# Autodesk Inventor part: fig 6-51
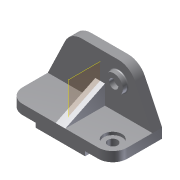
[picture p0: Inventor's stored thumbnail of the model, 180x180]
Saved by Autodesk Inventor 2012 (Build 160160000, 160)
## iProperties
Shininess: 77.0
Length Units: 11269
Angle Units: 11279
Time Units: 11290
Mass Units: 11283
Length Display Precision: 3
Angle Display Precision: 2
Created: 2001-12
Part Number: fig 6-51
Document SubType Name: Modeling
Designer: Renu Muthoo
Density: 1 g/cm^3
Material: Default
Density: 0.0
Volumn: 0.0
Area: 0.0
PropertySet Name: Model Information
Control State: 0
Master: False
Checked Out: False
Author: Renu Muthoo
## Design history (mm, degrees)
node "Sketch1"
sketch "Sketch2"
  geometry: L1 (-67.219, 19.116)-(148.781, 19.116); L2 (148.781, 19.116)-(148.781, -0.884); L3 (-67.219, -0.884)-(-67.219, 19.116); L4 (-10.219, -0.884)-(-10.219, -9.884); L5 (-10.219, -9.884)-(91.781, -9.884); L6 (91.781, -9.884)-(91.781, -0.884); L7 (148.781, -0.884)-(91.781, -0.884); L8 (-10.219, -0.884)-(-67.219, -0.884)
  constraints: 16 end point, 5 parallel, 4 perpendicular, 2 equal length, 1 horizontal
  dimensions: "d0" = 102 distance of L4.end L5.end; "d1" = 57 distance of L4.start L3.start; "d2" = 29 distance between parallel lines of L1 L5; "d3" = 20 distance of L1.end L2.end
extrude "Extrusion1" new body sketch "Sketch2" distance "d4" = 102; taper "d5" = 0 deg
sketch "Sketch3"
  geometry: L1 (67.219, -19.116)-(-148.781, -19.116) reference; L2 (67.219, -19.116)-(31.475, -93.564); L3 (-2.781, -115.116)-(-78.781, -115.116); L4 (-113.038, -93.564)-(-148.781, -19.116); A1 r 38 centre (-2.781, -77.116) between (-2.781, -115.116) and (31.475, -93.564); A2 r 38 centre (-78.781, -77.116) between (-113.038, -93.564) and (-78.781, -115.116)
  constraints: 6 end point, 4 point on circle, 4 tangent, 2 centre point, 1 equal length, 1 equal radius, 1 parallel
  dimensions: "d6" = 96 distance between parallel lines of L3 L1; "d7" = 38 radius of A1; "d8" = 76 distance of A2.centre A1.centre
extrude "Extrusion2" join sketch "Sketch3" distance "d9" = 20; taper "d10" = 0 deg
fillet "Fillet1" dims "d11" = 30
workplane "Work Plane1"
sketch "Sketch5"
  geometry: A1 r 30 centre (-30, 0) between (-30, -30) and (0, 0) reference; 1 further point
  constraints: 1 coincident
hole "Hole1" sketch "Sketch5" at (-30, 0) diameter "d16" = 20; stored, may be unused: countersink angle "d20" = 82 deg, drill point angle "d22" = 118 deg; dims "d17" = 6, "d18" = 38, "d19" = 6, "d21" = 8
sketch "Sketch6"
  geometry: C1 r 19 at (-2.781, 77.116); C2 r 9.5 at (-2.781, 77.116); A1 r 38 centre (-2.781, 77.116) between (31.475, 93.564) and (-2.781, 115.116) reference
  constraints: 2 centre point, 2 coincident
  dimensions: "d23" = 38 diameter of C1; "d24" = 19 diameter of C2
extrude "Extrusion3" join sketch "Sketch6" distance "d25" = 10; taper "d26" = 0 deg
sketch "Sketch7"
  geometry: L1 (0, -82)-(-39.557, 0); L2 (0, -82)-(20, -82) reference; L3 (29, 22.405)-(29, -82); L4 (29, -82)-(0, -82); L5 (0, -82)-(0, 0); L6 (0, 0)-(-90.034, 0); L7 (-90.034, 0)-(-90.034, 22.405); L8 (-90.034, 22.405)-(29, 22.405); L9 (0, 0)-(-74.447, 0) reference
  constraints: 14 end point, 1 collinear, 1 point on line
feature "Rib3" sketch "Sketch7" dims "d35" = 10, "d36" = 20
fillet "Fillet3" dims "d37" = 2
body "Solid1"
other parameters: "d12" = -108
